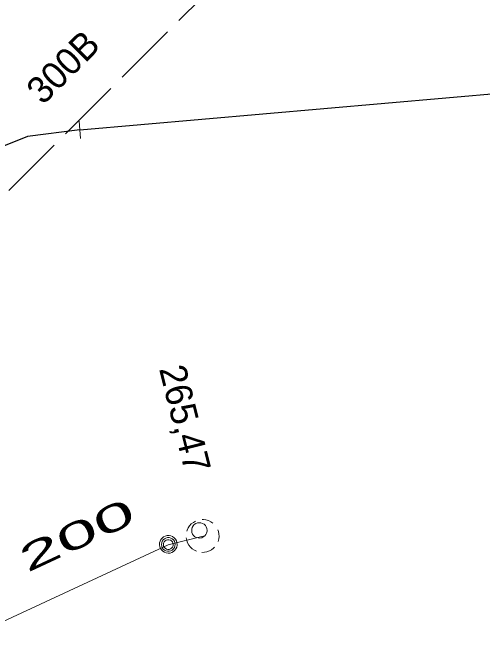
# Model space of a CAD drawing. Extents: x -732096 to -731933, y -1048703 to -1047964.
# Drawn here: x -732034.06 to -732019.99, y -1048481.66 to -1048462.87 of the extents above; entities that cross this region are included whole.
import ezdxf

# ---------------------------------------------------------------- set-up
doc = ezdxf.new("R2010")
doc.units = 0
doc.header["$LTSCALE"] = 0.32
doc.linetypes.add('LONG_DASHED', pattern=[7.5, 6, -1.5])
doc.layers.add('1', color=7, linetype='Continuous')
for name, color, linetype, lineweight in [('18', 7, 'Continuous', 13), ('20', 7, 'Continuous', 13), ('49', 7, 'Continuous', 13), ('8', 7, 'Continuous', 13)]:
    doc.layers.add(name, color=color, linetype=linetype, lineweight=lineweight)

msp = doc.modelspace()

# ---------------------------------------------------------------- linework, layer by layer
at = {"layer": '18'}
for points in [[(-732028.583, -1048478.109), (-732028.649, -1048478.148), (-732028.71, -1048478.196), (-732028.762, -1048478.252), (-732028.804, -1048478.316), (-732028.836, -1048478.387), (-732028.845, -1048478.412)], [(-732028.064, -1048478.171), (-732028.127, -1048478.129), (-732028.197, -1048478.096), (-732028.271, -1048478.073), (-732028.347, -1048478.064), (-732028.388, -1048478.063)], [(-732027.908, -1048478.721), (-732027.889, -1048478.647), (-732027.881, -1048478.571), (-732027.884, -1048478.494), (-732027.9, -1048478.419), (-732027.916, -1048478.371)], [(-732028.862, -1048478.615), (-732028.848, -1048478.69), (-732028.821, -1048478.763), (-732028.784, -1048478.829), (-732028.736, -1048478.89), (-732028.68, -1048478.942), (-732028.616, -1048478.985), (-732028.553, -1048479.015)], [(-732028.394, -1048479.049), (-732028.317, -1048479.046), (-732028.242, -1048479.032), (-732028.169, -1048479.005), (-732028.102, -1048478.968), (-732028.042, -1048478.921), (-732028.016, -1048478.896)]]:
    msp.add_lwpolyline(points, dxfattribs=at)
for points in [[(-732028.238, -1048478.389), (-732028.244, -1048478.337), (-732028.262, -1048478.287), (-732028.29, -1048478.243), (-732028.328, -1048478.206), (-732028.373, -1048478.179), (-732028.423, -1048478.163), (-732028.475, -1048478.158), (-732028.527, -1048478.165), (-732028.576, -1048478.184), (-732028.62, -1048478.214), (-732028.655, -1048478.253), (-732028.681, -1048478.298), (-732028.696, -1048478.349), (-732028.699, -1048478.401), (-732028.691, -1048478.453), (-732028.67, -1048478.501), (-732028.64, -1048478.544), (-732028.6, -1048478.579), (-732028.554, -1048478.603), (-732028.503, -1048478.617), (-732028.451, -1048478.619), (-732028.399, -1048478.609), (-732028.351, -1048478.587), (-732028.309, -1048478.555), (-732028.276, -1048478.515), (-732028.252, -1048478.468), (-732028.24, -1048478.417)], [(-732029.135, -1048478.807), (-732029.141, -1048478.751), (-732029.157, -1048478.698), (-732029.186, -1048478.649), (-732029.225, -1048478.608), (-732029.271, -1048478.576), (-732029.323, -1048478.554), (-732029.378, -1048478.543), (-732029.434, -1048478.545), (-732029.489, -1048478.558), (-732029.539, -1048478.583), (-732029.584, -1048478.618), (-732029.62, -1048478.661), (-732029.645, -1048478.711), (-732029.66, -1048478.766), (-732029.663, -1048478.822), (-732029.654, -1048478.877), (-732029.633, -1048478.93), (-732029.602, -1048478.976), (-732029.561, -1048479.015), (-732029.514, -1048479.045), (-732029.461, -1048479.064), (-732029.405, -1048479.071), (-732029.348, -1048479.067), (-732029.294, -1048479.05), (-732029.245, -1048479.023), (-732029.204, -1048478.985), (-732029.171, -1048478.94), (-732029.147, -1048478.889), (-732029.136, -1048478.834)], [(-732029.194, -1048478.81), (-732029.2, -1048478.761), (-732029.218, -1048478.715), (-732029.245, -1048478.674), (-732029.282, -1048478.641), (-732029.326, -1048478.619), (-732029.375, -1048478.607), (-732029.424, -1048478.607), (-732029.472, -1048478.619), (-732029.516, -1048478.642), (-732029.553, -1048478.675), (-732029.581, -1048478.716), (-732029.598, -1048478.763), (-732029.603, -1048478.812), (-732029.597, -1048478.861), (-732029.579, -1048478.907), (-732029.551, -1048478.947), (-732029.514, -1048478.98), (-732029.47, -1048479.002), (-732029.421, -1048479.014), (-732029.372, -1048479.013), (-732029.324, -1048479.001), (-732029.281, -1048478.977), (-732029.244, -1048478.944), (-732029.216, -1048478.903), (-732029.2, -1048478.856)], [(-732029.253, -1048478.814), (-732029.259, -1048478.772), (-732029.276, -1048478.734), (-732029.304, -1048478.703), (-732029.338, -1048478.68), (-732029.379, -1048478.669), (-732029.421, -1048478.669), (-732029.461, -1048478.681), (-732029.495, -1048478.704), (-732029.522, -1048478.736), (-732029.539, -1048478.774), (-732029.544, -1048478.815), (-732029.539, -1048478.857), (-732029.521, -1048478.894), (-732029.493, -1048478.926), (-732029.456, -1048478.948), (-732029.417, -1048478.959), (-732029.375, -1048478.958), (-732029.335, -1048478.945), (-732029.301, -1048478.922), (-732029.274, -1048478.889), (-732029.258, -1048478.851)]]:
    msp.add_lwpolyline(points, close=True, dxfattribs=at)
at = {"layer": '20', "linetype": 'LONG_DASHED'}
msp.add_line((-732035.87, -1048469.9), (-732026.27, -1048460.3), dxfattribs=at)
msp.add_line((-732035.87, -1048469.9), (-732026.27, -1048460.3), dxfattribs=at)
at = {"layer": '49'}
for p, q in [((-732028.359, -1048478.56), (-732029.399, -1048478.82)), ((-732028.359, -1048478.56), (-732029.399, -1048478.82)), ((-732029.399, -1048478.82), (-732035.513, -1048481.657)), ((-732029.399, -1048478.82), (-732035.513, -1048481.657))]:
    msp.add_line(p, q, dxfattribs=at)
at = {"layer": '8'}
msp.add_line((-732032.072, -1048466.131), (-732032.028, -1048466.646), dxfattribs=at)
at = {"layer": '8', "lineweight": 25}
for points in [[(-732032.05, -1048466.39), (-732015.611, -1048464.954), (-732004.39, -1048464), (-732002.395, -1048463.851)], [(-732032.05, -1048466.39), (-732033.616, -1048466.591), (-732038.16, -1048468.42), (-732043.974, -1048470.885)]]:
    msp.add_lwpolyline(points, dxfattribs=at)

# ---------------------------------------------------------------- texts
at = {"layer": '1'}
for s, rotation, p in [('300B', 45, (-732033.156, -1048465.668)), ('265,47', 284, (-732029.68, -1048473.548))]:
    msp.add_text(s, height=0.8, rotation=rotation, dxfattribs=at).set_placement(p)
at = {"layer": '1', "width": 2.05}
msp.add_text('200 ', height=0.8, rotation=25, dxfattribs=at).set_placement((-732033.626, -1048479.664))

doc.saveas('drawing.dxf')
